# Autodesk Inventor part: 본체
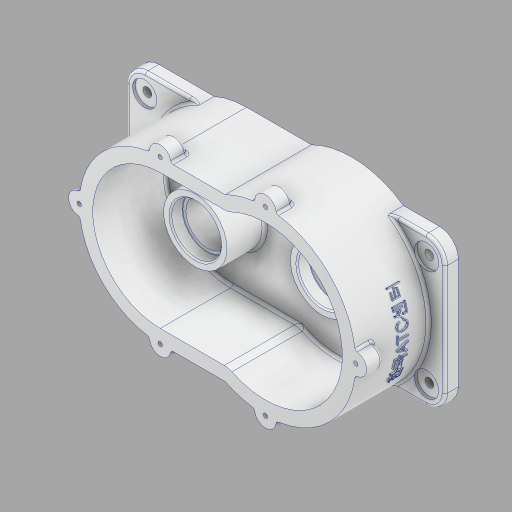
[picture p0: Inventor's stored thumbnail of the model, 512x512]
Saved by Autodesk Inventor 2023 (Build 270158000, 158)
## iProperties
Created: 2025-09
Part Number: 본체
Material: 알루미늄 6061
Document SubType Name: Modeling
Designer: home
Density: 2.7 g/cm^3
Appearance: 알루미늄 - 평지
Mass: 1589.33 g
Surface Area: 1306.5 cm^2
Volume: 588.641 cm^3
Author: home
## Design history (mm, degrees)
sketch "스케치1"
  geometry: L1 (118, -55)-(-118, -55); L2 (-118, -55)-(-118, 55); L3 (-118, 55)-(118, 55); L4 (118, 55)-(118, -55); L5 (118, -55)-(-118, 55); L6 (-118, -55)-(118, 55); 1 further point
  constraints: 12 end point, 2 midpoint, 2 parallel, 1 horizontal, 1 perpendicular
  dimensions: "d0" = 236 distance of L2.end L3.end; "d1" = 110 distance of L1.end L2.end
extrude "돌출1" new body sketch "스케치1" distance "d2" = 10; taper "d3" = 0 deg
sketch "스케치2"
  geometry: L1 (118, 55)-(-118, 55) reference; L2 (-118, 55)-(-118, -55) reference; L3 (-118, -55)-(118, -55) reference; L4 (118, -55)-(118, 55) reference; L5 (-39, -60)-(9.184, -60); L6 (-39, 60)-(9.184, 60); A1 r 67 centre (39, 0) between (9.184, -60) and (9.184, 60); A2 r 60 centre (-39, 0) between (-39, 60) and (-39, -60); 1 further point
  constraints: 4 end point, 4 point on circle, 2 centre point, 2 tangent, 1 horizontal, 1 parallel
  dimensions: "d10" = 134 diameter of A1; "d11" = 39 distance of point (0, 0) A2.centre; "d12" = 39 distance of A1.centre point (0, 0); "d13" = 55 distance from line of A1.centre L1; "d14" = 55 distance from line of A2.centre L1; "d15" = 60 radius of A2
extrude "돌출2" join sketch "스케치2" distance "d17" = 54; taper "d19" = 0 deg; dims "d18" = 10, "d20" = 0
sketch "스케치3"
  geometry: L1 (-39, -60)-(9.184, -60) reference; L2 (9.184, 60)-(-39, 60) reference; L3 (-39, 50)-(11.632, 50); L4 (-39, -50)-(11.632, -50); A1 r 60 centre (-39, 0) between (-39, 60) and (-39, -60) reference; A2 r 67 centre (39, 0) between (9.184, -60) and (9.184, 60) reference; A3 r 50 centre (-39, 0) between (-39, 50) and (-39, -50); A4 r 57 centre (39, 0) between (11.632, -50) and (11.632, 50); 1 further point
  constraints: 4 end point, 4 point on circle, 2 centre point, 2 coincident, 2 horizontal, 2 tangent
  dimensions: "d21" = 100 diameter of A3; "d22" = 114 diameter of A4
extrude "돌출3" cut sketch "스케치3" distance "d23" = 54; taper "d24" = 0 deg
sketch "스케치4"
  geometry: C1 r 23.5 at (-39, 0); A1 r 50 centre (-39, 0) between (-39, 50) and (-39, -50) reference; 1 further point
  constraints: 1 centre point, 1 coincident
  dimensions: "d25" = 47 diameter of C1
extrude "돌출4" join sketch "스케치4" distance "d26" = 28; taper "d27" = 0 deg
sketch "스케치5"
  geometry: C1 r 23.5 at (0, 0) reference; C2 r 18.5 at (0, 0); 1 further point
  constraints: 1 centre point, 1 coincident
  dimensions: "d28" = 37 diameter of C2
extrude "돌출5" cut sketch "스케치5" distance "d29" = 9; taper "d30" = 0 deg
sketch "스케치6"
  geometry: C1 r 18.5 at (0, 0) reference; C2 r 16 at (0, 0); 1 further point
  constraints: 1 centre point, 1 coincident
  dimensions: "d32" = 32 diameter of C2
extrude "돌출6" cut sketch "스케치6" distance "d33" = 16; taper "d34" = 0 deg
sketch "스케치7"
  geometry: C1 r 16 at (0, 0) reference; C2 r 14 at (0, 0); 1 further point
  constraints: 1 centre point, 1 coincident
  dimensions: "d35" = 28 diameter of C2
extrude "돌출7" cut sketch "스케치7" distance "d36" = 3; taper "d37" = 0 deg
chamfer "모따기1" distance "d38" = 1; stored, may be unused: second distance "d39" = 2, angle "d40" = 45 deg
fillet "모깎기1" dims "d41" = 0.3
fillet "모깎기2" dims "d42" = 2
sketch "스케치8"
  geometry: L1 (11.632, -50)-(-39, -50) reference; L2 (-39, 50)-(11.632, 50) reference; C1 r 23.5 at (-39, 0) reference; C2 r 23.5 at (39, 0); A1 r 57 centre (39, 0) between (11.632, -50) and (11.632, 50) reference; A2 r 50 centre (-39, 0) between (-39, 50) and (-39, -50) reference; 1 further point
  constraints: 1 centre point, 1 coincident
  dimensions: "d43" = 47 diameter of C2
extrude "돌출8" join sketch "스케치8" distance "d44" = 12; taper "d45" = 0 deg
sketch "스케치9"
  geometry: C1 r 23.5 at (0, 0) reference; C2 r 18.5 at (0, 0); 1 further point
  constraints: 1 centre point, 1 coincident
  dimensions: "d46" = 37 diameter of C2
extrude "돌출9" cut sketch "스케치9" distance "d47" = 9; taper "d48" = 0 deg
sketch "스케치10"
  geometry: C1 r 18.5 at (0, 0) reference; C2 r 15 at (0, 0); 1 further point
  constraints: 1 centre point, 1 coincident
  dimensions: "d49" = 30 diameter of C2
extrude "돌출10" cut sketch "스케치10" extent not by distance; stored distance "d50" = 9; taper "d51" = 0 deg
sketch "스케치11"
  geometry: L1 (-118, 55)-(-77.262, 55) reference; L2 (-118, -55)-(-118, 55) reference; L3 (-77.262, -55)-(-118, -55) reference; L4 (-9.184, -60)-(39, -60) reference; L5 (118, -55)-(62.979, -55) reference; L6 (118, 55)-(118, -55) reference; L7 (62.979, 55)-(118, 55) reference; L8 (39, 60)-(-9.184, 60) reference; C1 r 15 at (-39, 0) reference; C2 r 17.5 at (-39, 0); A1 r 67 centre (-39, 0) between (-77.262, -55) and (-9.184, -60) reference; A2 r 60 centre (39, 0) between (39, -60) and (62.979, -55) reference; A3 r 60 centre (39, 0) between (62.979, 55) and (39, 60) reference; A4 r 67 centre (-39, 0) between (-9.184, 60) and (-77.262, 55) reference; 1 further point
  constraints: 1 centre point, 1 coincident
  dimensions: "d52" = 35 diameter of C2
extrude "돌출11" cut sketch "스케치11" distance "d53" = 8.3; taper "d54" = 0 deg
chamfer "모따기2" distance "d55" = 0.8; stored, may be unused: second distance "d56" = 2, angle "d57" = 30 deg
fillet "모깎기3" dims "d58" = 0.3
chamfer "모따기3" distance "d59" = 1; stored, may be unused: second distance "d60" = 2, angle "d61" = 45 deg
fillet "모깎기4" dims "d62" = 2
sketch "스케치12"
  geometry: L1 (11.632, -50)-(-39, -50) reference; L2 (-39, 50)-(11.632, 50) reference; L3 (-39, -60)-(9.184, -60) reference; L4 (9.184, 60)-(-39, 60) reference; L5 (-29.202, 60)-(9.184, 60); L6 (9.184, -60)-(-39, -60) reference; L7 (-29.202, -60)-(9.184, -60); A1 r 57 centre (39, 0) between (11.632, -50) and (11.632, 50) reference; A2 r 50 centre (-39, 0) between (-39, 50) and (-39, -50) reference; A3 r 60 centre (-39, 0) between (-39, 60) and (-39, -60) reference; A4 r 67 centre (39, 0) between (9.184, -60) and (9.184, 60) reference; A5 r 8 centre (-99, 0) between (-99.96, 7.942) and (-99.96, -7.942); A6 r 60 centre (-39, 0) between (-39, 60) and (-62.979, 55) reference; A7 r 8 centre (-39, 60) between (-31.162, 61.6) and (-46.942, 60.96); A8 r 8 centre (-39, -60) between (-46.942, -60.96) and (-31.162, -61.6); A9 r 67 centre (39, 0) between (77.262, 55) and (9.184, 60) reference; A10 r 8 centre (39, 67) between (46.934, 68.027) and (31.066, 68.027); A11 r 67 centre (39, 0) between (77.262, -55) and (77.262, 55) reference; A12 r 8 centre (106, 0) between (107.027, -7.934) and (107.027, 7.934); A13 r 67 centre (39, 0) between (9.184, -60) and (77.262, -55) reference; A14 r 8 centre (39, -67) between (31.066, -68.027) and (46.934, -68.027); A15 r 67 centre (39, 0) between (-5.598, 50) and (-5.699, 49.91); A16 r 60 centre (-39, 0) between (-5.699, 49.91) and (-5.834, 50); A17 r 67 centre (39, 0) between (-5.699, -49.91) and (-5.598, -50); A18 r 60 centre (-39, 0) between (-5.834, -50) and (-5.699, -49.91); A19 r 67 centre (39, 0) between (9.184, -60) and (29.37, -66.304); A20 r 67 centre (39, 0) between (48.63, -66.304) and (105.304, -9.63); A21 r 67 centre (39, 0) between (105.304, 9.63) and (48.63, 66.304); A22 r 67 centre (39, 0) between (29.37, 66.304) and (9.184, 60); A23 r 60 centre (-39, 0) between (-48.607, 59.226) and (-98.226, 9.607); A24 r 60 centre (-39, 0) between (-98.226, -9.607) and (-48.607, -59.226); A25 r 2 centre (29.083, 68.284) between (29.37, 66.304) and (31.066, 68.027); A26 r 2 centre (48.917, 68.284) between (46.934, 68.027) and (48.63, 66.304); A27 r 2 centre (107.284, 9.917) between (105.304, 9.63) and (107.027, 7.934); A28 r 2 centre (107.284, -9.917) between (107.027, -7.934) and (105.304, -9.63); A29 r 2 centre (48.917, -68.284) between (48.63, -66.304) and (46.934, -68.027); A30 r 2 centre (29.083, -68.284) between (31.066, -68.027) and (29.37, -66.304); A31 r 2 centre (-29.202, -62) between (-29.202, -60) and (-31.162, -61.6); A32 r 2 centre (-48.928, -61.2) between (-46.942, -60.96) and (-48.607, -59.226); A33 r 2 centre (-100.2, -9.928) between (-98.226, -9.607) and (-99.96, -7.942); A34 r 2 centre (-100.2, 9.928) between (-99.96, 7.942) and (-98.226, 9.607); A35 r 2 centre (-48.928, 61.2) between (-48.607, 59.226) and (-46.942, 60.96); A36 r 2 centre (-29.202, 62) between (-31.162, 61.6) and (-29.202, 60); 15 further points
  constraints: 63 point on circle, 28 centre point, 28 tangent, 11 equal radius, 8 point on line, 7 end point, 3 coincident, 2 collinear
  dimensions: "d63" = 16 diameter of A5; "d64" = 16 diameter of A7; "d65" = 16 diameter of A8; "d66" = 16 diameter of A10; "d67" = 16 diameter of A12; "d68" = 16 diameter of A14; "d69" = 2 radius of A25 (derived); "d70" = 67 radius of A17; "d71" = 67 radius of A15; "d72" = 60 radius of A18; "d73" = 60 radius of A16; "d74" = 118.28358 distance from line of A26.centre L1; "d75" = 18.28358 distance from line of A29.centre L1
extrude "돌출12" join sketch "스케치12" distance "d76" = 12; taper "d77" = 0 deg
fillet "모깎기5" dims "d78" = 2
sketch "스케치13"
  geometry: L1 (11.632, -50)-(-39, -50) reference; L2 (-39, 50)-(11.632, 50) reference; L3 (-29.202, -60)-(9.184, -60) reference; L4 (9.184, 60)-(-29.202, 60) reference; L5 (-39, -60)-(-33.343, -60) reference; A1 r 57 centre (39, 0) between (11.632, -50) and (11.632, 50) reference; A2 r 50 centre (-39, 0) between (-39, 50) and (-39, -50) reference; A3 r 60 centre (-39, 0) between (-48.607, 59.226) and (-98.226, 9.607) reference; A4 r 2 centre (-100.2, 9.928) between (-99.96, 7.942) and (-98.226, 9.607) reference; A5 r 8 centre (-99, 0) between (-99.96, 7.942) and (-99.96, -7.942) reference; A6 r 2 centre (-100.2, -9.928) between (-98.226, -9.607) and (-99.96, -7.942) reference; A7 r 60 centre (-39, 0) between (-98.226, -9.607) and (-48.607, -59.226) reference; A8 r 2 centre (-48.928, -61.2) between (-46.942, -60.96) and (-48.607, -59.226) reference; A9 r 8 centre (-39, -60) between (-46.942, -60.96) and (-31.162, -61.6) reference; A10 r 2 centre (-29.202, -62) between (-29.202, -60) and (-31.162, -61.6) reference; A11 r 67 centre (39, 0) between (9.184, -60) and (29.37, -66.304) reference; A12 r 2 centre (29.083, -68.284) between (31.066, -68.027) and (29.37, -66.304) reference; A13 r 8 centre (39, -67) between (31.066, -68.027) and (46.934, -68.027) reference; A14 r 2 centre (48.917, -68.284) between (48.63, -66.304) and (46.934, -68.027) reference; A15 r 67 centre (39, 0) between (48.63, -66.304) and (105.304, -9.63) reference; A16 r 2 centre (107.284, -9.917) between (107.027, -7.934) and (105.304, -9.63) reference; A17 r 8 centre (106, 0) between (107.027, -7.934) and (107.027, 7.934) reference; A18 r 2 centre (107.284, 9.917) between (105.304, 9.63) and (107.027, 7.934) reference; A19 r 67 centre (39, 0) between (105.304, 9.63) and (48.63, 66.304) reference; A20 r 2 centre (48.917, 68.284) between (46.934, 68.027) and (48.63, 66.304) reference; A21 r 8 centre (39, 67) between (46.934, 68.027) and (31.066, 68.027) reference; A22 r 2 centre (29.083, 68.284) between (29.37, 66.304) and (31.066, 68.027) reference; A23 r 67 centre (39, 0) between (29.37, 66.304) and (9.184, 60) reference; A24 r 2 centre (-29.202, 62) between (-31.162, 61.6) and (-29.202, 60) reference; A25 r 8 centre (-39, 60) between (-31.162, 61.6) and (-46.942, 60.96) reference; A26 r 2 centre (-48.928, 61.2) between (-48.607, 59.226) and (-46.942, 60.96) reference; A27 r 8 centre (-99, 0) between (-99.96, 7.942) and (-99.96, -7.942) reference; 7 further points
  constraints: 6 coincident
hole "구멍1" sketch "스케치13" at (-99, 0), (-39, 60), (-39, -60), (39, -67), (39, 67), (106, 0) diameter "d79" = 3.242; stored, may be unused: countersink angle "d83" = 90 deg, drill point angle "d85" = 118 deg; dims "d80" = 8, "d81" = 4, "d82" = 2, "d84" = 10
fillet "모깎기6" dims "d86" = 14
sketch "스케치14"
  geometry: L1 (104.5, -41)-(-104.5, -41); L2 (-104.5, -41)-(-104.5, 41); L3 (-104.5, 41)-(104.5, 41); L4 (104.5, 41)-(104.5, -41); L5 (104.5, -41)-(-104.5, 41); L6 (-104.5, -41)-(104.5, 41); C1 r 3.3 at (-104.5, 41); C2 r 3.3 at (104.5, 41); C3 r 3.3 at (-104.5, -41); C4 r 3.3 at (104.5, -41); 1 further point
  constraints: 12 end point, 4 centre point, 3 coincident, 2 midpoint, 2 parallel, 1 horizontal, 1 perpendicular
  dimensions: "d87" = 209 distance of L2.end L3.end; "d88" = 82 distance of L1.end L2.end; "d89" = 6.6 diameter of C1; "d90" = 6.6 diameter of C2; "d91" = 6.6 diameter of C3; "d92" = 6.6 diameter of C4
extrude "돌출13" cut sketch "스케치14" extent not by distance; stored distance "d93" = 0; taper "d94" = 0 deg
sketch "스케치15"
  geometry: L1 (-118, 41)-(-118, -41) reference; L2 (-104, -55)-(-62.979, -55) reference; L3 (-62.979, 55)-(-104, 55) reference; L4 (104, 55)-(77.262, 55) reference; L5 (77.262, -55)-(104, -55) reference; L6 (118, -41)-(118, 41) reference; C1 r 3.3 at (-104.5, -41) reference; C2 r 3.3 at (-104.5, 41) reference; C3 r 3.3 at (104.5, -41) reference; C4 r 3.3 at (104.5, 41) reference; C5 r 3.3 at (-104.5, 41) reference; C6 r 9 at (-104.5, 41); C7 r 3.3 at (104.5, 41) reference; C8 r 9 at (104.5, 41); C9 r 3.3 at (-104.5, -41) reference; C10 r 9 at (-104.5, -41); C11 r 3.3 at (104.5, -41) reference; C12 r 9 at (104.5, -41); A1 r 14 centre (-104, 41) between (-104, 55) and (-118, 41) reference; A2 r 14 centre (-104, -41) between (-118, -41) and (-104, -55) reference; A3 r 60 centre (-39, 0) between (-62.979, 55) and (-62.979, -55) reference; A4 r 14 centre (104, 41) between (118, 41) and (104, 55) reference; A5 r 67 centre (39, 0) between (77.262, -55) and (77.262, 55) reference; A6 r 14 centre (104, -41) between (104, -55) and (118, -41) reference; 1 further point
  constraints: 4 centre point, 4 coincident
  dimensions: "d95" = 18 diameter of C6; "d96" = 18 diameter of C8; "d97" = 18 diameter of C10; "d98" = 18 diameter of C12
extrude "돌출14" cut sketch "스케치15" distance "d99" = 2; taper "d100" = 0 deg
fillet "모깎기7" dims "d101" = 2
node "작업 평면1"
sketch "스케치16"
  geometry: L1 (-22, 33.256)-(22, 33.256); L2 (22, 33.256)-(22, 26.744); L3 (22, 26.744)-(-22, 26.744); L4 (-22, 26.744)-(-22, 33.256); L5 (-41, 0)-(41, 0) reference; 5 further points
  constraints: 4 midpoint, 2 other
  dimensions: "d103" = 22 horizontal distance of L1.end point (0, 0); "d104" = 30 vertical distance of point (0, 0) point (22, 30); "d105" = 22 distance of point (0, 33.256) L1.start
feature "엠보싱1" sketch "스케치16" dims "d0" = 236, "d1" = 110, "d106" = 1, "d107" = 0
fillet "모깎기8" dims "d108" = 13
feature "ࠌ耀ࠎ耀ࠐ耀ࠒ耀ࠔ耀ࠖ耀࠘耀ࠚ耀" dims "d0" = 236, "d1" = 110, "d2" = 10, "d3" = 0, "d9" = 120, "d10" = 134, "d11" = 39, "d12" = 39, "d13" = 55, "d14" = 55, "d15" = 60, "d17" = 54, "d18" = 10, "d19" = 0, "d20" = 0, "d21" = 100, "d22" = 114, "d23" = 54, "d24" = 0, "d25" = 47, "d26" = 28, "d27" = 0, "d28" = 37, "d29" = 9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
node "솔리드1"
node "투영된 루프1"
node "투영된 루프2"
node "투영된 루프3"
node "투영된 루프4"
node "투영된 루프5"
node "투영된 루프6"
node "투영된 루프7"
node "투영된 루프8"
node "투영된 루프9"
node "투영된 루프10"
node "투영된 루프11"
node "투영된 루프12"
node "투영된 루프13"
feature "A9D066F2-1C7D-4E18-AEED-F7BC21143FA4" dims "d79" = 3.242, "d80" = 8, "d81" = 4, "d82" = 2, "d83" = 90 deg, "d84" = 10, "d85" = 118 deg
